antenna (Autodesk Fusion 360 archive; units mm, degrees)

design "antenna" references "stand"
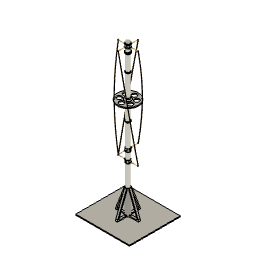
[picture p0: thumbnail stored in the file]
sketch "Sketch1" plane through (0, 0, 0) normal (0, 1, 0) x axis (1, 0, 0)
  circle C1 centre (0, 0) radius 20.6
  circle C2 centre (0, 0) radius 22.6
  point P1 (0, 0)
  point P2 (0, 0)
  coincident P1 P2
  concentric C1 C2
  dimension "d1" diameter C1 = 41.2
  dimension "d2" diameter C2 = 45.2
sphere_primitive "SpherePrimitive1" Diameter 45.2
extrude "Extrude1" cut sketch "Sketch1" along normal blind 24
extrude "Extrude2" add sketch "Sketch1" along normal blind 10
shell "Shell1" innerThickness 3
work_plane "WorkPlane1" AlongDistance 0
sketch "Sketch3" plane through (0, 10, 0) normal (0, 1, 0) x axis (1, 0, 0)
  circle C1 centre (0, 0) radius 22.6
  circle C2 centre (0, 0) radius 20.6
extrude "Extrude3" new body sketch "Sketch3" along normal blind 30
sketch "Sketch4" plane through (0, 0, 0) normal (1, 0, 0) x axis (0, 0, -1)
  line L1 (0, 25) -> (0, 0)
  circle C1 centre (0, 25) radius 4.1
  circle C2 centre (0, 25) radius 6.1
  point P1 (0, 0)
  point P2 (0, 0)
  point P3 (0, 25)
  point P4 (0, 25)
  coincident P1 P2
  vertical L1
  coincident P3 P4
  concentric C1 C2
  dimension "d12" distance P2 P3 = 25
  dimension "d13" diameter C1 = 8.2
  dimension "d14" diameter C2 = 12.2
extrude "Extrude4" new body sketch "Sketch4" profile of C1 C2 along normal blind 32.5 and against normal blind 32.5
extrude "Extrude5" cut sketch "Sketch1" profile of C1 along normal blind 55
extrude "Extrude6" cut sketch "Sketch4" profile of C1 distance 45
sketch "Sketch5" plane through (0, 0, 0) normal (0, 0, 1) x axis (1, 0, 0)
  line L1 (0, 25) -> (0, 0)
  circle C1 centre (0, 25) radius 4.1
  circle C2 centre (0, 25) radius 6.1
  point P1 (0, 0)
  point P2 (0, 0)
  point P3 (0, 25)
  point P4 (0, 25)
  coincident P1 P2
  vertical L1
  coincident P3 P4
  concentric C1 C2
  dimension "d23" distance P2 P3 = 25
  dimension "d24" diameter C1 = 8.2
  dimension "d25" diameter C2 = 12.2
extrude "Extrude7" new body sketch "Sketch5" profile of C1 C2 distance 32.5
extrude "Extrude8" cut sketch "Sketch5" profile of C1 distance 38
extrude "Extrude9" cut sketch "Sketch1" profile of C1 along normal blind 55
combine "Combine1"
fillet "Fillet1" radius 10
fillet "Fillet2" radius 10
fillet "Fillet3" radius 10
fillet "Fillet4" radius 10
copy_paste_bodies "CopyPasteBodies1"
move "Move1"
work_plane "WorkPlane2" AlongDistance 0
sketch "Sketch6" plane through (0, 70, 0) normal (0, 1, 0) x axis (1, 0, 0)
  circle C1 centre (0, 0) radius 22.6
  circle C2 centre (0, 0) radius 20.6
sketch "Sketch7" plane through (0, 0, 0) normal (0, 1, 0) x axis (1, 0, 0)
  line L1 (-28, 28) -> (28, 28)
  line L2 (-28, -28) -> (-28, 28)
  line L3 (28, -28) -> (-28, -28)
  line L4 (28, 28) -> (28, -28)
  line L5 (-28, -28) -> (28, 28)
  line L6 (28, -28) -> (-28, 28)
  line L7 (-50.7066, 54.5262) -> (50.7066, 54.5262)
  line L8 (-50.7066, -54.5262) -> (-50.7066, 54.5262)
  line L9 (50.7066, -54.5262) -> (-50.7066, -54.5262)
  line L10 (50.7066, 54.5262) -> (50.7066, -54.5262)
  line L11 (-50.7066, -54.5262) -> (50.7066, 54.5262)
  line L12 (50.7066, -54.5262) -> (-50.7066, 54.5262)
  point P6 (0, 0)
  point P1 (0, 0)
  point P11 (0, 0)
  point P4 (-28, -28)
  point P5 (28, -28)
  point P3 (-28, 28)
  horizontal L1
  perpendicular L1 L2
  parallel L1 L3
  parallel L2 L4
  coincident L5 P6
  coincident L6 P6
  coincident P1 P6
  horizontal L7
  perpendicular L7 L8
  parallel L7 L9
  parallel L8 L10
  coincident L11 P11
  coincident L12 P11
  coincident P6 P11
  dimension "d41" distance P4 P5 = 56
  dimension "d42" distance P3 P4 = 56
work_plane "WorkPlane3" sketch "Sketch6" AlongDistance 0
sketch "Sketch8" plane through (0, 70, 0) normal (0, 1, 0) x axis (1, 0, 0)
  line L1 (15.9806, -15.9806) -> (0, 0)
  line L2 (22.6, 0) -> (0, 0)
  line L3 (14.2836, -17.6777) -> (-1.6971, -1.6971)
  line L4 (17.6777, -14.2836) -> (1.6971, 1.6971)
  circle C1 centre (0, 0) radius 22.6
  circle C2 centre (0, 0) radius 20.6
  circle C3 centre (16.4226, -16.4226) radius 2.75
  circle C4 centre (16.4226, -16.4226) radius 4.75
  point P2 (0, 0)
  point P4 (0, 0)
  horizontal L2
  coincident P2 P4
  dimension "d46" angle L1 L2 = 45
  dimension "d47" diameter C3 = 5.5
  dimension "d48" = 2
  dimension "d53" = 2.4
  dimension "d54" = -2.4
extrude "Extrude10" new body sketch "Sketch8" profile of C1 C2 along normal blind 10
extrude "Extrude11" add sketch "Sketch8" profile of C1 C3 C4 along normal blind 10
extrude "Extrude12" cut sketch "Sketch8" profile of C1 C3 along normal blind 10
extrude "Extrude13" cut of existing geometry blind -10
extrude "Extrude14" new body sketch "Sketch8" profile of C1 C2 C3 C4 L3 L4 along normal blind 10
sketch "Sketch9" plane through (0, 70, 0) normal (0, 1, 0) x axis (1, 0, 0)
work_plane "WorkPlane4" AlongDistance 0
sketch "Sketch10" plane through (0, 70, 0) normal (0, 1, 0) x axis (1, 0, 0)
  curve K1 (-22.2333, -4.0548) -> (-22.2333, 4.0548)
  curve K2 (-4.0548, 22.2333) -> (4.0548, 22.2333)
  curve K3 (22.2333, 4.0548) -> (22.2333, -4.0548)
  curve K4 (4.0548, -22.2333) -> (-4.0548, -22.2333)
  line L1 (-16.2391, 38.8342) -> (16.2391, 38.8342)
  line L2 (-16.2391, -38.026) -> (-16.2391, 38.8342)
  line L3 (16.2391, -38.026) -> (-16.2391, -38.026)
  line L4 (16.2391, 38.8342) -> (16.2391, -38.026)
  circle C1 centre (0, 0) radius 20.6
  arc A1 centre (0, 0) radius 22.6 clockwise from (-4.0548, -22.2333) to (-22.2333, -4.0548)
  arc A2 centre (0, 0) radius 22.6 clockwise from (-22.2333, 4.0548) to (-4.0548, 22.2333)
  arc A3 centre (0, 0) radius 22.6 clockwise from (4.0548, 22.2333) to (22.2333, 4.0548)
  arc A4 centre (0, 0) radius 22.6 clockwise from (22.2333, -4.0548) to (4.0548, -22.2333)
  horizontal L1
  vertical L2
  horizontal L3
  vertical L4
extrude "Extrude15" cut sketch "Sketch10" profile of A1 A2 K2 A3 A4 K4 L1 L2 L3 L4 against normal blind 47
sketch "Sketch11" plane through (0, 0, 0) normal (0, 0, 1) x axis (1, 0, 0)
  curve K1 (4.0548, 54.3927) -> (-4.0548, 54.3927)
  curve K2 (-4.0548, 55.6073) -> (4.0548, 55.6073)
  curve K3 (4.0548, 55.6073) -> (4.0548, 54.3927)
  curve K4 (-4.0548, 54.3927) -> (-4.0548, 55.6073)
extrude "Extrude16" add of existing geometry blind -26
work_plane "WorkPlane5" AlongDistance 0
sketch "Sketch12" plane through (32.5, 0, 0) normal (1, 0, 0) x axis (0, 0, -1)
  curve K1 (-0.9667, 48.9771) -> (0.9667, 48.9771)
  curve K2 (0.9667, 61.0229) -> (-0.9667, 61.0229)
  circle C1 centre (0, 55) radius 4.1
  arc A1 centre (0, 55) radius 6.1 clockwise from (-0.9667, 48.9771) to (-0.9667, 61.0229)
  arc A2 centre (0, 55) radius 6.1 clockwise from (0.9667, 61.0229) to (0.9667, 48.9771)
work_plane "WorkPlane6" sketch "Sketch12" AlongDistance 0
sketch "Sketch13" plane through (32.5, 55, 0) normal (1, 0, 0) x axis (0, 0, -1)
  curve K1 (-4.0548, -0.6073) -> (4.0548, -0.6073)
  line L1 (4.0548, 0.6072) -> (4.0548, -0.6073)
  curve K2 (4.0548, 0.6072) -> (-4.0548, 0.6072)
  line L2 (-4.0548, -0.6073) -> (-4.0548, 0.6072)
extrude "Extrude17" cut sketch "Sketch13" against normal blind 91
extrude "Extrude18" new body sketch "Sketch3" profile of C2 along normal blind 1490 and against normal blind 10
work_plane "WorkPlane7" AlongDistance 0
sketch "Sketch14" plane through (0, 1500, 0) normal (0, 1, 0) x axis (1, 0, 0)
  circle C1 centre (0, 0) radius 20.6
  circle C2 centre (0, 0) radius 19.475
  point P1 (0, 0)
  point P2 (0, 0)
  point P3 (0, 0)
  coincident P1 P2
  coincident P1 P3
  dimension "d73" diameter C1 = 41.2
  dimension "d74" diameter C2 = 38.95
extrude "Extrude19" cut sketch "Sketch14" profile of C2 against normal blind 1700
move "Move2"
move "Move3"
copy_paste_bodies "CopyPasteBodies2"
move "Move4"
copy_paste_bodies "CopyPasteBodies3"
move "Move5"
work_plane "WorkPlane8" AlongDistance 0
sketch "Sketch15" plane through (-0.3296, 910, -0.3296) normal (0, -1, 0) x axis (-1, 0, 0)
  line L1 (-14.1057, -17.4999) -> (-13.0997, -16.4939)
  line L2 (-16.4939, -13.0997) -> (-17.4999, -14.1057)
  line L3 (-16.5687, 38.5046) -> (-16.5687, -38.3555)
  line L4 (-18.0073, -14.6131) -> (-2.0266, 1.3675)
  line L5 (-14.6131, -18.0073) -> (1.3675, -2.0266)
  line L6 (-14.6558, -11.2617) -> (-16.4939, -13.0997)
  line L7 (-11.2617, -14.6558) -> (-14.6558, -11.2617)
  arc A1 centre (-0.3296, -0.3296) radius 20.6 clockwise from (-16.4939, -13.0997) to (-13.0997, -16.4939)
  arc A2 centre (-16.7521, -16.7521) radius 2.75 clockwise from (-14.1057, -17.4999) to (-17.4999, -14.1057)
  arc A3 centre (-16.7521, -16.7521) radius 4.75 clockwise from (-12.7056, -19.2397) to (-19.2397, -12.7056)
  arc A4 centre (-0.3296, -0.3296) radius 22.6 clockwise from (-19.2397, -12.7056) to (-12.7056, -19.2397)
  circle C1 centre (-0.3296, -0.3296) radius 22.6
  circle C2 centre (-0.3296, -0.3296) radius 20.6
  circle C3 centre (-16.7521, -16.7521) radius 2.75
  circle C4 centre (-16.7521, -16.7521) radius 2.75
  circle C5 centre (-16.7521, -16.7521) radius 4.75
  point P3 (-16.4939, -13.0997)
  point P19 (-16.4939, -13.0997)
  point P20 (-14.6558, -11.2617)
  point P21 (-11.2617, -14.6558)
  coincident P3 P19
  coincident L4 P20
  parallel L4 L6
  coincident L5 P21
  perpendicular L5 L7
  concentric C3 C4
  concentric C4 C5
extrude "Extrude20" cut sketch "Sketch15" profile of L1 A2 L2 C1 C2 C3 L3 L4 L5 L6 C4 C5 against normal blind 30
extrude "Extrude21" add sketch "Sketch15" profile of A1 L1 A2 L2 A3 C1 C2 C3 L3 L4 L5 C4 C5 against normal blind 30
work_plane "WorkPlane9" AlongDistance 0
sketch "Sketch16" plane through (-0.329, 1040, -0.0006) normal (0, 1, 0) x axis (1, 0, 0)
  line L1 (16.4932, -12.7708) -> (17.4993, -13.7768)
  line L2 (14.6125, -17.6783) -> (-1.3681, -1.6977)
  line L3 (18.0067, -14.2842) -> (2.026, 1.6965)
  line L4 (11.2611, -14.3268) -> (14.6552, -10.9327)
  circle C1 centre (16.7515, -16.4232) radius 2.75
  circle C2 centre (16.7515, -16.4232) radius 4.75
  circle C3 centre (0.329, -0.0006) radius 22.6
  circle C4 centre (0.329, -0.0006) radius 20.6
extrude "Extrude22" cut sketch "Sketch16" profile of C1 C2 C3 C4 L1 L2 L3 against normal blind 30
extrude "Extrude23" add sketch "Sketch16" profile of C1 C2 C3 C4 L1 L2 L3 against normal blind 30
extrude "Extrude24" cut of existing geometry blind -1500
work_plane "WorkPlane10" AlongDistance 22.5
sketch "Sketch17" plane through (22.5, 0, 0) normal (1, 0, 0) x axis (0, 0, -1)
  circle C1 centre (0.0001, 1024.9997) radius 2.5
  dimension "d90" diameter C1 = 5
extrude "Extrude25" cut sketch "Sketch17" against normal blind 54
sketch "Sketch18" plane through (0, 0, 0) normal (1, 0, 0) x axis (0, 0, -1)
sketch "Sketch19" plane through (0, 70, 0) normal (0, 1, 0) x axis (1, 0, 0)
work_plane "WorkPlane11" AlongDistance -45
sketch "Sketch20" plane through (0, 25, 0) normal (0, 1, 0) x axis (1, 0, 0)
  line L1 (0, -100) -> (0, 0)
  line L2 (100, 0) -> (0, 0)
  line L3 (0, 100) -> (0, 0)
  line L4 (-100, 0) -> (0, 0)
  circle C1 centre (0, 0) radius 100
  point P1 (0, 0)
  point P2 (0, 0)
  point P3 (0, 0)
  point P4 (0, -100)
  point P5 (0, 0)
  point P6 (100, 0)
  point P7 (0, 0)
  point P8 (0, 100)
  point P9 (0, 0)
  point P10 (-100, 0)
  coincident P1 P2
  coincident P2 P3
  coincident C1 P4
  vertical L1
  coincident P1 P5
  coincident C1 P6
  perpendicular L1 L2
  coincident P1 P7
  coincident C1 P8
  perpendicular L2 L3
  coincident P2 P9
  coincident C1 P10
  perpendicular L1 L4
  dimension "d94" diameter C1 = 200
work_plane "WorkPlane12" AlongDistance 1000
sketch "Sketch21" plane through (0, 1025, 0) normal (0, 1, 0) x axis (1, 0, 0)
sketch "Sketch22" plane through (0, 1025, 0) normal (0, 1, 0) x axis (1, 0, 0)
  line L1 (-100, 0) -> (0, 0)
  line L2 (0, -100) -> (0, 0)
  line L3 (100, 0) -> (0, 0)
  line L4 (0, 100) -> (0, 0)
  circle C1 centre (0, 0) radius 100
work_plane "WorkPlane13" AlongDistance 500
sketch "Sketch23" plane through (0, 525, 0) normal (0, 1, 0) x axis (1, 0, 0)
  line L1 (0, -100) -> (0, 0)
  line L2 (100, 0) -> (0, 0)
  line L3 (0, 100) -> (0, 0)
  line L4 (-100, 0) -> (0, 0)
  line L5 (70.7107, 70.7107) -> (0, 0)
  line L6 (100, 0) -> (0, 0)
  line L7 (70.7107, -70.7107) -> (0, 0)
  line L8 (100, 0) -> (0, 0)
  line L9 (-70.7107, -70.7107) -> (0, 0)
  line L10 (100, 0) -> (0, 0)
  line L11 (-70.7107, 70.7107) -> (0, 0)
  curve K1 (100, 0) -> (0, 100)
  curve K2 (-100, 0) -> (0, -100)
  circle C1 centre (0, 0) radius 100
  point P6 (0, 0)
  point P12 (0, 0)
  point P4 (0, 0)
  point P15 (0, 0)
  point P18 (0, 0)
  point P22 (0, 100)
  point P24 (0, 100)
  point P23 (100, 0)
  point P25 (100, 0)
  point P26 (0, -100)
  point P28 (0, -100)
  point P27 (-100, 0)
  point P29 (-100, 0)
  horizontal L6
  coincident P6 P12
  horizontal L8
  coincident P4 P15
  horizontal L10
  coincident P4 P18
  coincident P22 P24
  coincident P23 P25
  coincident P26 P28
  coincident P27 P29
  dimension "d97" angle L5 L6 = 45
  dimension "d98" angle L7 L8 = 45
  dimension "d99" angle L9 L10 = 135
  dimension "d100" angle L9 L11 = 90
work_plane "WorkPlane14" AlongDistance 900
sketch "Sketch24" plane through (0, 925, 0) normal (0, 1, 0) x axis (1, 0, 0)
  line L1 (-100, 0) -> (0, 0)
  line L2 (0, -100) -> (0, 0)
  line L3 (100, 0) -> (0, 0)
  line L4 (0, 100) -> (0, 0)
  circle C1 centre (0, 0) radius 100
work_plane "WorkPlane15" AlongDistance 450
sketch "Sketch25" plane through (0, 475, 0) normal (0, 1, 0) x axis (1, 0, 0)
  line L1 (0, -100) -> (0, 0)
  line L2 (100, 0) -> (0, 0)
  line L3 (0, 100) -> (0, 0)
  line L4 (-100, 0) -> (0, 0)
  line L5 (70.7107, 70.7107) -> (0, 0)
  line L6 (100, 0) -> (0, 0)
  line L7 (70.7107, -70.7107) -> (0, 0)
  line L8 (100, 0) -> (0, 0)
  line L9 (-70.7107, -70.7107) -> (0, 0)
  line L10 (100, 0) -> (0, 0)
  line L11 (-70.7107, 70.7107) -> (0, 0)
  line L12 (100, 0) -> (0, 0)
  curve K1 (0, -100) -> (100, 0)
  curve K2 (0, 100) -> (-100, 0)
  circle C1 centre (0, 0) radius 100
  point P5 (0, 0)
  point P13 (0, 0)
  point P9 (0, 0)
  point P18 (0, 0)
  point P2 (0, 0)
  point P21 (0, 0)
  point P24 (100, 0)
  point P26 (100, 0)
  point P25 (0, -100)
  point P27 (0, -100)
  point P28 (-100, 0)
  point P30 (-100, 0)
  point P29 (0, 100)
  point P31 (0, 100)
  horizontal L6
  coincident P5 P13
  horizontal L8
  horizontal L10
  coincident P9 P18
  horizontal L12
  coincident P2 P21
  coincident P24 P26
  coincident P25 P27
  coincident P28 P30
  coincident P29 P31
  dimension "d103" angle L5 L6 = 45
  dimension "d104" angle L7 L8 = 45
  dimension "d105" angle L9 L10 = 135
  dimension "d106" angle L11 L12 = 135
move "Move6" RotateAngle -90
move "Move7" RotateAngle -90
move "Move8" RotateAngle -90
move "Move9" RotateAngle -90
pipe "Pipe1" SectionSize 8 SectionThickness 1
pipe "Pipe2" SectionSize 8 SectionThickness 1
pipe "Pipe3" SectionSize 8 SectionThickness 1
pipe "Pipe5" SectionSize 8 SectionThickness 1
pipe "Pipe6" SectionSize 8 SectionThickness 1
pipe "Pipe7" SectionSize 8 SectionThickness 1
pipe "Pipe8" SectionSize 8 SectionThickness 1
sketch "Sketch27" plane through (0, 25, 0) normal (0, 1, 0) x axis (1, 0, 0)
  line L1 (-10, 0) -> (-100, 0)
  line L2 (10, -10) -> (-10, -10)
  line L3 (10, 10) -> (10, -10)
  line L4 (-10, 10) -> (10, 10)
  line L5 (-10, -10) -> (-10, 10)
  line L6 (10, 10) -> (-10, -10)
  line L7 (-10, 10) -> (10, -10)
  point P2 (-100, 0)
  point P3 (-100, 0)
  point P9 (0, 0)
  point P1 (0, 0)
  point P4 (-10, 0)
  point P7 (10, 10)
  point P8 (-10, 10)
  point P6 (10, -10)
  coincident P2 P3
  horizontal L2
  perpendicular L2 L3
  parallel L2 L4
  parallel L3 L5
  coincident L6 P9
  coincident L7 P9
  coincident P1 P9
  dimension "d144" distance P3 P4 = 90
  dimension "d145" distance P7 P8 = 20
  dimension "d146" distance P6 P7 = 20
extrude "Extrude26" cut sketch "Sketch27" profile of L2 L3 L4 L5 distance 20
combine "Combine1"
sketch "Sketch28" plane through (0, 0, 0) normal (0, 1, 0) x axis (1, 0, 0)
  circle C1 centre (0, 0) radius 20.5
  circle C2 centre (0, 0) radius 19.5
  point P1 (0, 0)
  point P2 (0, 0)
  point P3 (0, 0)
  coincident P1 P2
  coincident P1 P3
  dimension "d149" diameter C1 = 41
  dimension "d150" diameter C2 = 39
extrude "Extrude1" new body sketch "Sketch28" along normal blind 1500
work_plane "WorkPlane16" RotateAngle -45
sketch "Sketch29" plane through (-14.4957, 131.2117, 14.4957) normal (-0.7071, 0, 0.7071) x axis (-0.7071, 0, -0.7071)
  line L1 (20.5, -1368.7883) -> (-20.5, -1368.7883)
  line L2 (20.5, 131.2117) -> (-20.5, 131.2117)
  line L3 (0, 31.2117) -> (0, 131.2117)
  circle C1 centre (0, 31.2117) radius 3
  point P6 (0, 131.2117)
  point P7 (0, 31.2117)
  point P8 (0, 31.2117)
  midpoint L2 P6
  perpendicular L2 L3
  coincident P7 P8
  dimension "d154" distance P6 P7 = 100
  dimension "d155" diameter C1 = 6
extrude "Extrude2" cut sketch "Sketch29" profile of C1 against normal blind 10
work_plane "WorkPlane17" AlongDistance 0
sketch "Sketch30" plane through (-0.0074, 25.0416, 101.9996) normal (0.1757, -0.9842, 0.0211) x axis (0, -0.0215, -0.9998)
work_plane "WorkPlane18" AlongDistance 25
work_plane "WorkPlane19" AlongDistance 25
sketch "Sketch31" plane through (0, 25, 0) normal (0, 1, 0) x axis (1, 0, 0)
  line L1 (0, -100) -> (0, 0)
  line L2 (0, 100) -> (0, 0)
  line L3 (100, 0) -> (0, 0)
  line L4 (-100, 0) -> (0, 0)
  circle C1 centre (0, 0) radius 100
  point P1 (0, 0)
  point P2 (0, 0)
  point P3 (0, 0)
  point P4 (0, -100)
  point P5 (0, 0)
  point P6 (0, 100)
  point P7 (0, 0)
  point P8 (100, 0)
  point P9 (0, 0)
  point P10 (-100, 0)
  coincident P1 P2
  coincident P2 P3
  coincident C1 P4
  vertical L1
  coincident P1 P5
  coincident C1 P6
  parallel L1 L2
  coincident P2 P7
  coincident C1 P8
  perpendicular L2 L3
  coincident P2 P9
  coincident C1 P10
  perpendicular L2 L4
  dimension "d161" diameter C1 = 200
sphere_primitive "SpherePrimitive3" sketch "Sketch31" Diameter 8
move "Move10"
sphere_primitive "SpherePrimitive4" sketch "Sketch31" Diameter 8
move "Move11"
sphere_primitive "SpherePrimitive5" sketch "Sketch31" Diameter 8
move "Move12"
sphere_primitive "SpherePrimitive6" sketch "Sketch31" Diameter 8
move "Move13"
combine "Combine1"
combine "Combine1"
work_plane "WorkPlane20" AlongDistance 1000
sketch "Sketch36" plane through (0, 1025, 0) normal (0, 1, 0) x axis (1, 0, 0)
  line L1 (0, -100) -> (0, 0)
  line L2 (0, 100) -> (0, 0)
  line L3 (0, -100) -> (0, 0)
  line L4 (0, 100) -> (0, 0)
  circle C1 centre (0, 0) radius 100
  point P1 (0, 0)
  point P2 (0, 0)
  point P3 (0, 0)
  point P5 (0, 0)
  point P7 (0, 0)
  point P9 (0, 0)
  point P6 (0, 100)
  point P8 (0, -100)
  point P10 (0, 100)
  coincident P1 P2
  vertical L1
  coincident P1 P3
  coincident P2 P5
  parallel L1 L2
  coincident P1 P7
  parallel L1 L3
  vertical L4
  coincident P2 P9
  dimension "d167" diameter C1 = 200
  dimension "d168" distance P5 P6 = 100
  dimension "d169" distance P7 P8 = 100
  dimension "d170" distance P9 P10 = 100
sphere_primitive "SpherePrimitive7" sketch "Sketch36" Diameter 8
move_face "MoveFace1"
sphere_primitive "SpherePrimitive8" sketch "Sketch36" Diameter 8
move_face "MoveFace2"
move_face "MoveFace3"
move_face "MoveFace4"
combine "Combine1"
move_face "MoveFace5"
combine "Combine1"
combine "Combine1"
sketch "Sketch39" plane through (-0.3296, 910, -0.3296) normal (0, -1, 0) x axis (-1, 0, 0)
  line L1 (0, 100) -> (0, 0)
  line L2 (0, -100) -> (0, 0)
  circle C1 centre (0, 0) radius 100
  point P1 (0, 0)
  point P2 (0, 0)
  point P3 (0, 0)
  point P4 (0, 100)
  point P5 (0, 0)
  point P6 (0, -100)
  coincident P1 P2
  coincident P1 P3
  coincident C1 P4
  vertical L1
  coincident P2 P5
  coincident C1 P6
  parallel L1 L2
  dimension "d173" diameter C1 = 200
sphere_primitive "SpherePrimitive9" sketch "Sketch39" Diameter 8
move_face "MoveFace6"
copy_paste_bodies "CopyPasteBodies4"
move "Move14"
combine "Combine1"
move "Move1" RotateAngle -180
work_plane "WorkPlane21" AlongDistance 0
sketch "Sketch41" plane through (0, 0, 0) normal (0, 1, 0) x axis (1, 0, 0)
sketch "Sketch42" plane through (0, 0, 0) normal (0, 1, 0) x axis (1, 0, 0)
  line L1 (-12.5, 12.5) -> (12.5, -12.5)
  line L2 (12.5, 12.5) -> (-12.5, -12.5)
  circle C1 centre (0, 12.5) radius 1.5
  circle C2 centre (12.5, 0) radius 1.5
  circle C3 centre (0, -12.5) radius 1.5
  circle C4 centre (-12.5, 0) radius 1.5
  point P6 (0, 0)
  point P1 (0, 0)
  point P4 (-12.5, 12.5)
  point P5 (12.5, 12.5)
  point P3 (-12.5, -12.5)
  coincident L1 P6
  coincident L2 P6
  coincident P1 P6
  dimension "d182" distance P4 P5 = 25
  dimension "d183" distance P3 P4 = 25
  dimension "d184" diameter C1 = 3
  dimension "d185" diameter C2 = 3
  dimension "d186" diameter C3 = 3
  dimension "d187" diameter C4 = 3
extrude "Extrude1" cut sketch "Sketch42" profile of C1 C2 C3 C4 against normal blind 36
work_plane "WorkPlane22" AlongDistance -495
sketch "Sketch43" plane through (0, -495, 0) normal (0, 1, 0) x axis (1, 0, 0)
  circle C1 centre (0, 0) radius 20.5
  circle C2 centre (0, 0) radius 106
  concentric C1 C2
  dimension "d197" diameter C1 = 41
  dimension "d198" diameter C2 = 212
delete_face "DeleteFace1"
combine "Combine1"
combine "Combine1"
extrude "Extrude27" new body sketch "Sketch43" distance 5
copy_paste_bodies "CopyPasteBodies5"
place_component sketch "Sketch44"
combine "Combine1" sketch "Sketch44"
copy_paste_bodies "CopyPasteBodies6"
combine "Combine1"
copy_paste_bodies "CopyPasteBodies7"
copy_paste_bodies "CopyPasteBodies8"
combine "Combine2"
remove_body "RemoveBody17"
remove_body "RemoveBody18"
remove_body "RemoveBody19"
remove_body "RemoveBody20"
work_plane "WorkPlane23" AlongDistance 0
sketch "Sketch44" plane through (0, -490, 0) normal (0, 1, 0) x axis (1, 0, 0)
  line L1 (-17.1703, 13.7762) -> (-16.1643, 12.7701)
  line L2 (-12.7701, 16.1643) -> (-13.7762, 17.1703)
  line L3 (0, 55) -> (0, 0)
  line L4 (0, 65) -> (0, 55)
  arc A1 centre (0, 0) radius 20.6 clockwise from (-12.7701, 16.1643) to (-16.1643, 12.7701)
  arc A2 centre (-16.4226, 16.4226) radius 2.75 clockwise from (-17.1703, 13.7762) to (-13.7762, 17.1703)
  arc A3 centre (-16.4226, 16.4226) radius 4.75 clockwise from (-18.9102, 12.376) to (-12.376, 18.9102)
  arc A4 centre (0, 0) radius 22.6 clockwise from (-12.376, 18.9102) to (-18.9102, 12.376)
  circle C1 centre (0, 65) radius 25
  circle C2 centre (-56.2917, 32.5) radius 25
  circle C3 centre (-56.2917, -32.5) radius 25
  circle C4 centre (0, -65) radius 25
  circle C5 centre (56.2917, -32.5) radius 25
  circle C6 centre (56.2917, 32.5) radius 25
  point P4 (0, 0)
  point P10 (0, 0)
  point P12 (0, 65)
  point P13 (0, 65)
  point P11 (0, 55)
  vertical L3
  coincident P4 P10
  parallel L3 L4
  coincident P12 P13
  dimension "d210" distance P10 P11 = 55
  dimension "d211" distance P11 P12 = 10
  dimension "d212" diameter C1 = 50
  dimension "d214" C-Pattern1-Angle = 360
extrude "Extrude28" cut sketch "Sketch44" profile of A1 L1 A2 L2 against normal blind 12
extrude "Extrude29" add sketch "Sketch44" profile of A1 L1 A2 L2 A3 A4 along normal blind 20
fillet "Fillet6" radius 10
extrude "Extrude30" cut sketch "Sketch44" profile of C1 C2 C3 C4 C5 C6 against normal blind 50
move "Move16"
work_plane "WorkPlane24" AlongDistance 10
sketch "Sketch45" plane through (0, 0, 0) normal (0, 1, 0) x axis (1, 0, 0)
work_plane "WorkPlane25" AlongDistance 0
sketch "Sketch46" plane through (0, -10, 0) normal (0, 1, 0) x axis (1, 0, 0)
  circle C1 centre (0, 0) radius 20.5
  circle C2 centre (0, 0) radius 19.5
  point P2 (0, 0)
  point P3 (0, 0)
  coincident P2 P3
  concentric C1 C2
  dimension "d221" diameter C1 = 41
  dimension "d222" diameter C2 = 39
extrude "Extrude31" new body sketch "Sketch46" against normal blind 1500
work_plane "WorkPlane26" AlongDistance 0
sketch "Sketch47" plane through (0, 0, 0) normal (0, 1, 0) x axis (1, 0, 0)
sphere_primitive "SpherePrimitive10" Diameter 8
move_face "MoveFace7"
copy_paste_bodies "CopyPasteBodies9"
move "Move17"
combine "Combine3"
component_insert "Component Insert"
move "Move18"
position "Position1"
work_plane "WorkPlane27" AlongDistance 0
sketch "Sketch49" plane through (0, -1500, 0) normal (0, -1, 0) x axis (-1, 0, 0)
  line L1 (-270, -255) -> (270, -255)
  line L2 (-270, 255) -> (-270, -255)
  line L3 (270, 255) -> (-270, 255)
  line L4 (270, -255) -> (270, 255)
  line L5 (-270, 255) -> (270, -255)
  line L6 (270, 255) -> (-270, -255)
  point P6 (0, 0)
  point P1 (0, 0)
  point P4 (-270, 255)
  point P5 (270, 255)
  point P3 (-270, -255)
  horizontal L1
  perpendicular L1 L2
  parallel L1 L3
  parallel L2 L4
  coincident L5 P6
  coincident L6 P6
  coincident P1 P6
  dimension "d228" distance P4 P5 = 540
  dimension "d229" distance P3 P4 = 510
extrude "Extrude32" new body sketch "Sketch49" profile of L1 L2 L3 L4 along normal blind 9
work_plane "WorkPlane28" AlongDistance -70
work_plane "WorkPlane29" AlongDistance -5
work_plane "WorkPlane30" AlongDistance -5
work_plane "WorkPlane31" AlongDistance -5
work_plane "WorkPlane32" AlongDistance -1.25
work_plane "WorkPlane33" AlongDistance -1.25
work_plane "WorkPlane34" AlongDistance -1.25
sketch "Sketch50" plane through (0, -70, 0) normal (0, 1, 0) x axis (1, 0, 0)
  line L1 (16.2635, 16.2635) -> (0, 0)
  line L2 (-16.2635, 16.2635) -> (0, 0)
  line L3 (16.2635, -16.2635) -> (0, 0)
  line L4 (23, 0) -> (0, 0)
  line L5 (-16.2635, -16.2635) -> (0, 0)
  line L6 (23, 0) -> (0, 0)
  line L7 (16.2635, 16.2635) -> (0, 0)
  circle C1 centre (0, 0) radius 23
  point P1 (0, 0)
  point P2 (0, 0)
  point P3 (0, 0)
  point P4 (0, 0)
  point P6 (0, 0)
  point P10 (0, 0)
  point P5 (16.2635, 16.2635)
  coincident P1 P2
  coincident P1 P3
  coincident P1 P4
  coincident P1 P6
  horizontal L4
  horizontal L6
  coincident P2 P10
  perpendicular L2 L7
  dimension "d239" diameter C1 = 46
  dimension "d253" distance P4 P5 = 23
  dimension "d255" angle L3 L4 = 45
  dimension "d256" angle L5 L6 = 135
sketch "Sketch51" plane through (0, -71.25, 0) normal (0, 1, 0) x axis (1, 0, 0)
  line L1 (23, 0) -> (0, 0)
  line L2 (-16.2635, 16.2635) -> (0, 0)
  line L3 (16.2635, 16.2635) -> (0, 0)
  line L4 (15.7731, -15.7731) -> (0, 0)
  line L5 (23, 0) -> (0, 0)
  line L6 (-16.2635, -16.2635) -> (0, 0)
  circle C1 centre (0, 0) radius 23
  point P2 (0, 0)
  point P11 (0, 0)
  point P12 (-16.2635, -16.2635)
  horizontal L5
  coincident P2 P11
  dimension "d259" angle L4 L5 = 45
  dimension "d261" distance P11 P12 = 23
sketch "Sketch52" plane through (0, -72.5, 0) normal (0, 1, 0) x axis (1, 0, 0)
sketch "Sketch53" plane through (0, -70, 0) normal (0, 1, 0) x axis (1, 0, 0)
sketch "Sketch54" plane through (0, -72.5, 0) normal (0, 1, 0) x axis (1, 0, 0)
  line L1 (-16.2635, 16.2635) -> (0, 0)
  line L2 (-16.2635, -16.2635) -> (0, 0)
  line L3 (16.2635, -16.2635) -> (0, 0)
  line L4 (16.2635, 16.2635) -> (0, 0)
  circle C1 centre (0, 0) radius 23
sketch "Sketch55" plane through (0, -73.75, 0) normal (0, 1, 0) x axis (1, 0, 0)
  line L1 (-16.2635, 16.2635) -> (0, 0)
  line L2 (16.2635, 16.2635) -> (0, 0)
  line L3 (16.2635, -16.2635) -> (0, 0)
  line L4 (-16.2635, -16.2635) -> (0, 0)
  circle C1 centre (0, 0) radius 23
sketch "Sketch56" plane through (0, -75, 0) normal (0, 1, 0) x axis (1, 0, 0)
  line L1 (-16.2635, 16.2635) -> (0, 0)
  line L2 (16.2635, 16.2635) -> (0, 0)
  line L3 (16.2635, -16.2635) -> (0, 0)
  line L4 (-16.2635, -16.2635) -> (0, 0)
  circle C1 centre (0, 0) radius 23
work_plane "WorkPlane35" AlongDistance 1.25
work_plane "WorkPlane36" AlongDistance 1.25
work_plane "WorkPlane37" AlongDistance 1.25
work_plane "WorkPlane38" AlongDistance 1.25
work_plane "WorkPlane39" AlongDistance 1.25
work_plane "WorkPlane40" AlongDistance 1.25
work_plane "WorkPlane41" AlongDistance 1.25
sketch "Sketch57" plane through (0, -85, 0) normal (0, 1, 0) x axis (1, 0, 0)
  line L1 (-16.259, 16.2679) -> (0, 0)
  line L2 (16.2679, 16.259) -> (0, 0)
  line L3 (16.259, -16.2679) -> (0, 0)
  line L4 (-16.2679, -16.259) -> (0, 0)
  circle C1 centre (0, 0) radius 23
  point P2 (0, 0)
  point P3 (0, 0)
  point P4 (-16.259, 16.2679)
  point P6 (16.2679, 16.259)
  point P8 (16.259, -16.2679)
  point P10 (-16.2679, -16.259)
  coincident P2 P3
  coincident C1 P4
  coincident C1 P6
  perpendicular L1 L2
  coincident C1 P8
  perpendicular L2 L3
  coincident C1 P10
  perpendicular L3 L4
sketch "Sketch58" plane through (0, -76.25, 0) normal (0, 1, 0) x axis (1, 0, 0)
  line L1 (-16.2635, 16.2635) -> (0, 0)
  line L2 (16.2635, 16.2635) -> (0, 0)
  line L3 (16.2635, -16.2635) -> (0, 0)
  line L4 (-16.2635, -16.2635) -> (0, 0)
  circle C1 centre (0, 0) radius 23
sketch "Sketch59" plane through (0, -77.5, 0) normal (0, 1, 0) x axis (1, 0, 0)
  line L1 (-16.2635, 16.2635) -> (0, 0)
  line L2 (-16.2635, -16.2635) -> (0, 0)
  line L3 (16.2635, 16.2635) -> (0, 0)
  line L4 (16.2635, -16.2635) -> (0, 0)
  circle C1 centre (0, 0) radius 23
sketch "Sketch60" plane through (0, -78.75, 0) normal (0, 1, 0) x axis (1, 0, 0)
  line L1 (-16.2635, 16.2635) -> (0, 0)
  line L2 (16.2635, 16.2635) -> (0, 0)
  line L3 (16.2635, -16.2635) -> (0, 0)
  line L4 (-16.2635, -16.2635) -> (0, 0)
  circle C1 centre (0, 0) radius 23
sketch "Sketch61" plane through (0, -80, 0) normal (0, 1, 0) x axis (1, 0, 0)
  line L1 (-16.2635, 16.2635) -> (0, 0)
  line L2 (16.2635, 16.2635) -> (0, 0)
  line L3 (16.2635, -16.2635) -> (0, 0)
  line L4 (-16.2635, -16.2635) -> (0, 0)
  circle C1 centre (0, 0) radius 23
sketch "Sketch62" plane through (0, -81.25, 0) normal (0, 1, 0) x axis (1, 0, 0)
  line L1 (-16.2635, 16.2635) -> (0, 0)
  line L2 (16.2635, 16.2635) -> (0, 0)
  line L3 (16.2635, -16.2635) -> (0, 0)
  line L4 (-16.2635, -16.2635) -> (0, 0)
  circle C1 centre (0, 0) radius 23
sketch "Sketch63" plane through (0, -82.5, 0) normal (0, 1, 0) x axis (1, 0, 0)
  line L1 (-16.2635, -16.2635) -> (0, 0)
  line L2 (16.2635, -16.2635) -> (0, 0)
  line L3 (16.2635, 16.2635) -> (0, 0)
  line L4 (-16.2635, 16.2635) -> (0, 0)
  circle C1 centre (0, 0) radius 23
sketch "Sketch64" plane through (0, -83.75, 0) normal (0, 1, 0) x axis (1, 0, 0)
  line L1 (-16.2635, 16.2635) -> (0, 0)
  line L2 (-16.2635, -16.2635) -> (0, 0)
  line L3 (16.2635, 16.2635) -> (0, 0)
  line L4 (16.2635, -16.2635) -> (0, 0)
  circle C1 centre (0, 0) radius 23
work_plane "WorkPlane43" sketch "Sketch57" AlongDistance -1.25
work_plane "WorkPlane44" AlongDistance -1.25
work_plane "WorkPlane45" AlongDistance -1.25
work_plane "WorkPlane46" AlongDistance -1.25
sketch "Sketch65" plane through (-0.0044, -90, 16.2635) normal (0, 1, 0) x axis (1, 0, 0)
  line L1 (16.2723, 32.5225) -> (0.0044, 16.2635)
  line L2 (-16.2546, 32.5314) -> (0.0044, 16.2635)
  line L3 (-16.2635, 0.0044) -> (0.0044, 16.2635)
  line L4 (16.2635, -0.0044) -> (0.0044, 16.2635)
  circle C1 centre (0.0044, 16.2635) radius 23
sketch "Sketch66" plane through (-0.0044, -88.75, 16.2635) normal (0, 1, 0) x axis (1, 0, 0)
  line L1 (16.2723, 32.5225) -> (0.0044, 16.2635)
  line L2 (-16.2546, 32.5314) -> (0.0044, 16.2635)
  line L3 (-16.2635, 0.0044) -> (0.0044, 16.2635)
  line L4 (16.2635, -0.0044) -> (0.0044, 16.2635)
  circle C1 centre (0.0044, 16.2635) radius 23
sketch "Sketch67" plane through (-0.0044, -87.5, 16.2635) normal (0, 1, 0) x axis (1, 0, 0)
  line L1 (16.2635, -0.0044) -> (0.0044, 16.2635)
  line L2 (-16.2635, 0.0044) -> (0.0044, 16.2635)
  line L3 (-16.2546, 32.5314) -> (0.0044, 16.2635)
  line L4 (16.2723, 32.5225) -> (0.0044, 16.2635)
  circle C1 centre (0.0044, 16.2635) radius 23
sketch "Sketch68" plane through (-0.0044, -86.25, 16.2635) normal (0, 1, 0) x axis (1, 0, 0)
  line L1 (16.2723, 32.5225) -> (0.0044, 16.2635)
  line L2 (-16.2546, 32.5314) -> (0.0044, 16.2635)
  line L3 (16.2635, -0.0044) -> (0.0044, 16.2635)
  line L4 (-16.2635, 0.0044) -> (0.0044, 16.2635)
  circle C1 centre (0.0044, 16.2635) radius 23
work_plane "WorkPlane47" sketch "Sketch57" AlongDistance 1.25
sketch "Sketch69" plane through (-16.2635, -83.75, -0.0044) normal (0, 1, 0) x axis (1, 0, 0)
  line L1 (0, -16.2679) -> (16.2635, -0.0044)
  line L2 (32.5314, 16.2546) -> (16.2635, -0.0044)
  line L3 (0, 16.259) -> (16.2635, -0.0044)
  curve K1 (0, 16.259) -> (0.0044, 16.2635)
  circle C1 centre (16.2635, -0.0044) radius 23
  circle C2 centre (16.2635, -0.0044) radius 19.5
  point P14 (0.0044, 16.2635)
  point P15 (0.0044, 16.2635)
  point P13 (-0.0044, -16.2635)
  point P16 (-0.0044, -16.2635)
  point P12 (32.5225, -16.2723)
  point P17 (32.5225, -16.2723)
  point P11 (32.5314, 16.2546)
  point P18 (32.5314, 16.2546)
  point P10 (0.0044, 16.2635)
  point P19 (0.0044, 16.2635)
  point P4 (0, -16.2679)
  point P20 (0, -16.2679)
  point P21 (32.5269, -16.2679)
  point P32 (32.5269, -16.2679)
  point P22 (32.5269, 16.259)
  point P33 (32.5269, 16.259)
  point P23 (0, 16.259)
  point P34 (0, 16.259)
  point P24 (0, -16.2679)
  point P35 (0, -16.2679)
  point P25 (32.5269, -16.2679)
  point P36 (32.5269, -16.2679)
  point P26 (32.5269, 16.259)
  point P37 (32.5269, 16.259)
  point P27 (0, 16.259)
  point P38 (0, 16.259)
  point P28 (0, -16.2679)
  point P39 (0, -16.2679)
  point P29 (32.5269, -16.2679)
  point P40 (32.5269, -16.2679)
  point P30 (32.5269, 16.259)
  point P41 (32.5269, 16.259)
  point P31 (0, 16.259)
  point P42 (0, 16.259)
  coincident P14 P15
  coincident P13 P16
  coincident P12 P17
  coincident P11 P18
  coincident P10 P19
  coincident P4 P20
  coincident P21 P32
  coincident P22 P33
  coincident P23 P34
  coincident P24 P35
  coincident P25 P36
  coincident P26 P37
  coincident P27 P38
  coincident P28 P39
  coincident P29 P40
  coincident P30 P41
  coincident P31 P42
pipe "Pipe10" SectionSize 5 SectionThickness 1.25
work_plane "WorkPlane48" AlongDistance 0
sketch "Sketch70" plane through (-16.2338, -90.0709, -16.2492) normal (0.5515, -0.024, -0.8338) x axis (-0.8341, 0, -0.5517)
sphere_primitive "SpherePrimitive11" Diameter 5
sphere_primitive "SpherePrimitive12" Diameter 5
move_face "MoveFace8"
combine "Combine4"
work_plane "WorkPlane49" AlongDistance 0
sketch "Sketch73" plane through (0, -1500, 0) normal (0, 1, 0) x axis (1, 0, 0)
  circle C1 centre (-16.2635, 16.2635) radius 2.5
  point P2 (-16.2635, 16.2635)
  point P3 (-16.2635, 16.2635)
  coincident P2 P3
  dimension "d275" diameter C1 = 5
extrude "Extrude33" new body sketch "Sketch73" along normal blind 1410
combine "Combine5"
extrude "Extrude34" cut of existing geometry blind -3
move "Move19"
sphere_primitive "SpherePrimitive13" Diameter 8
move "Move20"
copy_paste_bodies "CopyPasteBodies10"
move "Move21"
combine "Combine6"
sphere_primitive "SpherePrimitive2" Diameter 8
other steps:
move "Move1" RotateAngle -180
move "Move1" RotateAngle -180
move "Move1" RotateAngle -180
move "Move1" RotateAngle -180
extrude "Extrude1" cut sketch "Sketch44" profile of C1 C2 C3 C4 C5 C6 against normal blind 50
extrude "Extrude1" cut sketch "Sketch42" profile of C1 C2 C3 C4 against normal blind 36
extrude "Extrude1" cut sketch "Sketch42" profile of C1 C2 C3 C4 against normal blind 36
extrude "Extrude1" cut sketch "Sketch42" profile of C1 C2 C3 C4 against normal blind 36
base_feature "Base Feature1"
base_feature "Base Feature2"
base_feature "Base Feature3"
base_feature "Base Feature4"
move "Move15" RotateAngle -180
base_feature "Base Feature5"
base_feature "Base Feature6"
base_feature "Base Feature7"
base_feature "Base Feature8"
base_feature "Base Feature9"
base_feature "Base Feature10"
create_component "CreateComponent1"
remove_body "RemoveBody1"
remove_body "RemoveBody2"
remove_body "RemoveBody3"
remove_body "RemoveBody4"
remove_body "RemoveBody5"
remove_body "RemoveBody6"
remove_body "RemoveBody7"
remove_body "RemoveBody8"
remove_body "RemoveBody9"
create_component "CreateComponent2"
create_component "CreateComponent3"
remove_body "RemoveBody10"
remove_body "RemoveBody11"
create_component "CreateComponent4"
remove_body "RemoveBody1"
remove_body "RemoveBody12"
create_component "CreateComponent5"
remove_body "RemoveBody2"
create_component "CreateComponent6"
remove_body "RemoveBody1"
create_component "CreateComponent7"
remove_body "RemoveBody1"
create_component "CreateComponent8"
remove_body "RemoveBody13"
remove_body "RemoveBody14"
create_component "CreateComponent9"
remove_body "RemoveBody15"
remove_body "RemoveBody16"
create_component "CreateComponent10"
remove_body "RemoveBody1"
create_component "CreateComponent11" sketch "Sketch44"
remove_body "RemoveBody1"
create_component "CreateComponent12"
remove_body "RemoveBody1"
